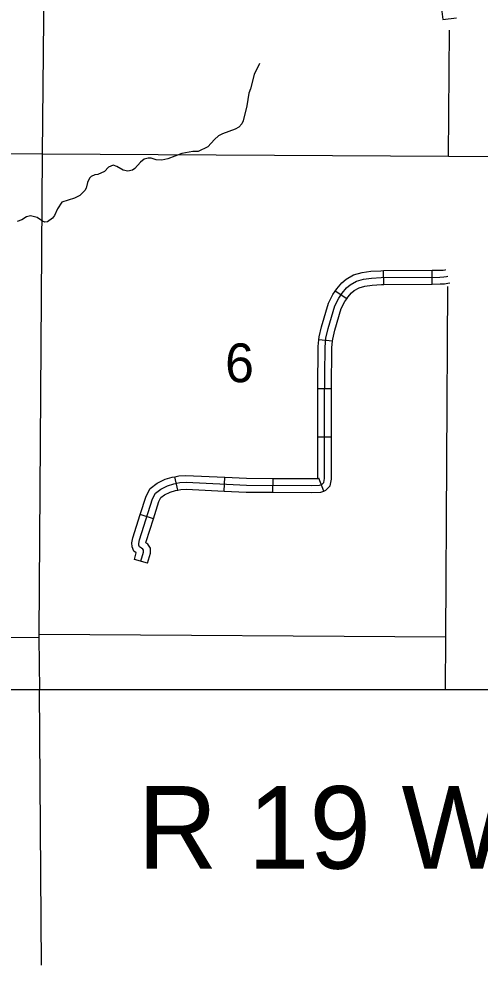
# Model space of a CAD drawing. Extents: x 1374139 to 1377472, y 1168351 to 1170484.
# Drawn here: x 1375695.3 to 1375795.8, y 1168593.8 to 1168800 of the extents above; entities that cross this region are included whole.
import ezdxf

# ---------------------------------------------------------------- set-up
doc = ezdxf.new("R2010")
doc.units = 0
for name, color, linetype in [('14', 7, 'Continuous'), ('26', 7, 'Continuous'), ('Default', 7, 'Continuous')]:
    doc.layers.add(name, color=color, linetype=linetype)

msp = doc.modelspace()

# ---------------------------------------------------------------- linework, layer by layer
at = {"layer": '14'}
msp.add_line((1375700.26, 1168593.79), (1375699.77, 1168653.79), dxfattribs=at)
at = {"layer": '26'}
msp.add_lwpolyline([(1375090, 1169579.43), (1376597.43, 1169579.43), (1376597.43, 1168653.79), (1375090, 1168653.79)], close=True, dxfattribs=at)
at = {"layer": 'Default'}
for p, q in [((1375788.95, 1168770.03), (1375841.85, 1168769.82)), ((1375774.82, 1168742.11), (1375774.8, 1168745.11)), ((1375785.38, 1168742.18), (1375785.36, 1168745.18)), ((1375766.76, 1168738.99), (1375764.27, 1168740.67)), ((1375763.67, 1168729.74), (1375760.69, 1168730.06)), ((1375763.46, 1168719.34), (1375760.46, 1168719.36)), ((1375763.44, 1168708.79), (1375760.44, 1168708.79)), ((1375729.92, 1168697.28), (1375729.3, 1168700.21)), ((1375740.07, 1168697.09), (1375740.21, 1168700.08)), ((1375750.69, 1168696.83), (1375750.7, 1168699.83)), ((1375761.77, 1168697.09), (1375760.68, 1168699.88)), ((1375724.61, 1168691.06), (1375721.75, 1168691.97)), ((1375723.35, 1168681.35), (1375720.47, 1168682.19))]:
    msp.add_line(p, q, dxfattribs=at)
for points in [[(1375700.72, 1168807.29), (1375700.37, 1168770.59)], [(1375787.36, 1168808.46), (1375787.35, 1168808.15), (1375787.5, 1168801.57), (1375787.69, 1168799.87), (1375790.67, 1168800.21)], [(1375788.95, 1168770.03), (1375789.16, 1168797.52)], [(1375747.72, 1168790.26), (1375746.58, 1168787.86), (1375745.78, 1168784.73), (1375745.44, 1168783.8), (1375744.97, 1168781.04), (1375744.22, 1168777.73), (1375743.91, 1168777.08), (1375743.25, 1168776.4), (1375742.44, 1168775.94), (1375739.67, 1168774.91), (1375738.82, 1168774.45), (1375737.94, 1168773.72), (1375736.48, 1168772.06), (1375734.38, 1168771.09), (1375733.22, 1168771.1), (1375730.79, 1168770.64), (1375727.74, 1168769.44), (1375726.49, 1168769.15), (1375725.21, 1168769.24), (1375724.1, 1168769.59), (1375723.5, 1168769.63), (1375722.58, 1168769.43), (1375721.78, 1168768.73), (1375720.61, 1168767.4), (1375720.06, 1168767.02), (1375719.05, 1168766.8), (1375718.06, 1168767.01), (1375716.68, 1168767.84), (1375715.87, 1168768.06), (1375714.85, 1168767.64), (1375713.99, 1168766.71), (1375712.54, 1168766.09), (1375711.89, 1168765.98), (1375711.04, 1168765.59), (1375710.7, 1168765.29), (1375710.23, 1168764.35), (1375709.94, 1168763.08), (1375709.65, 1168762.59), (1375708.6, 1168761.5), (1375707.39, 1168760.87), (1375704.67, 1168760.04), (1375703.71, 1168758.61), (1375703.03, 1168757.11), (1375702.64, 1168756.56), (1375701.54, 1168755.73), (1375700.92, 1168755.65), (1375700.42, 1168755.9), (1375699.3, 1168756.72), (1375697.85, 1168757.04), (1375696.99, 1168756.8), (1375695.97, 1168756.17), (1375694.96, 1168755.79)], [(1375623.44, 1168770.62), (1375700.37, 1168770.59)], [(1375700.37, 1168770.59), (1375699.67, 1168665.86), (1375699.68, 1168665.11), (1375699.77, 1168653.79)], [(1375700.37, 1168770.59), (1375788.95, 1168770.03)], [(1375721.91, 1168681.77), (1375722.49, 1168683.75), (1375722.49, 1168684.18), (1375722.32, 1168684.43), (1375722.02, 1168684.65), (1375721.57, 1168684.95), (1375721.44, 1168685.27), (1375721.42, 1168685.67), (1375721.59, 1168686.48), (1375724.41, 1168695.41), (1375725.05, 1168696.65), (1375726.22, 1168697.52), (1375727.72, 1168698.25), (1375729.08, 1168698.63), (1375730.41, 1168698.91), (1375731.73, 1168699), (1375744.88, 1168698.36), (1375759.06, 1168698.29), (1375760.83, 1168698.33), (1375761.32, 1168698.53), (1375761.75, 1168698.97), (1375761.94, 1168699.81), (1375761.94, 1168716.53), (1375762.03, 1168728.47), (1375762.24, 1168730.43), (1375762.69, 1168732.48), (1375764.16, 1168737.45), (1375765.04, 1168739.13), (1375765.77, 1168740.21), (1375766.73, 1168741.36), (1375767.49, 1168742), (1375768.86, 1168742.79), (1375770.42, 1168743.22), (1375772.14, 1168743.48), (1375774.26, 1168743.6), (1375787.08, 1168743.7), (1375787.92, 1168743.75), (1375788.51, 1168743.82), (1375788.8, 1168743.91)], [(1375764.27, 1168740.67), (1375764.57, 1168741.12), (1375765.66, 1168742.42), (1375766.63, 1168743.23), (1375768.27, 1168744.19), (1375770.11, 1168744.69), (1375771.99, 1168744.97), (1375774.21, 1168745.1), (1375774.8, 1168745.11)], [(1375774.8, 1168745.11), (1375785.36, 1168745.18)], [(1375785.36, 1168745.18), (1375787.03, 1168745.19), (1375787.78, 1168745.24), (1375788.21, 1168745.3), (1375788.38, 1168745.35)], [(1375766.76, 1168738.99), (1375766.98, 1168739.31), (1375767.79, 1168740.3), (1375768.35, 1168740.77), (1375769.44, 1168741.4), (1375770.72, 1168741.75), (1375772.3, 1168741.98), (1375774.31, 1168742.1), (1375774.82, 1168742.11)], [(1375774.82, 1168742.11), (1375785.38, 1168742.18)], [(1375785.38, 1168742.18), (1375787.14, 1168742.2), (1375788.06, 1168742.25), (1375788.82, 1168742.35), (1375789.21, 1168742.46)], [(1375788.32, 1168653.79), (1375788.34, 1168665.24), (1375788.78, 1168741.63)], [(1375760.69, 1168730.06), (1375760.76, 1168730.67), (1375761.24, 1168732.85), (1375762.77, 1168738.02), (1375763.75, 1168739.9), (1375764.27, 1168740.67)], [(1375763.67, 1168729.74), (1375763.72, 1168730.19), (1375764.14, 1168732.11), (1375765.56, 1168736.89), (1375766.33, 1168738.36), (1375766.76, 1168738.99)], [(1375760.46, 1168719.36), (1375760.53, 1168728.55), (1375760.69, 1168730.06)], [(1375763.46, 1168719.34), (1375763.53, 1168728.38), (1375763.67, 1168729.74)], [(1375760.44, 1168708.79), (1375760.44, 1168716.53), (1375760.46, 1168719.36)], [(1375763.44, 1168708.79), (1375763.44, 1168716.52), (1375763.46, 1168719.34)], [(1375760.4, 1168699.77), (1375760.44, 1168699.98), (1375760.44, 1168708.79)], [(1375761.77, 1168697.09), (1375762.18, 1168697.25), (1375763.12, 1168698.24), (1375763.44, 1168699.64), (1375763.44, 1168708.79)], [(1375721.75, 1168691.97), (1375723.02, 1168695.98), (1375723.88, 1168697.64), (1375725.44, 1168698.81), (1375727.18, 1168699.66), (1375728.73, 1168700.09), (1375729.3, 1168700.21)], [(1375729.3, 1168700.21), (1375730.2, 1168700.4), (1375731.72, 1168700.5), (1375740.21, 1168700.08)], [(1375740.21, 1168700.08), (1375744.92, 1168699.86), (1375750.7, 1168699.83)], [(1375750.7, 1168699.83), (1375759.05, 1168699.79), (1375760.53, 1168699.83), (1375760.68, 1168699.88)], [(1375724.61, 1168691.06), (1375725.8, 1168694.83), (1375726.22, 1168695.65), (1375727.01, 1168696.24), (1375728.25, 1168696.84), (1375729.44, 1168697.18), (1375729.92, 1168697.28)], [(1375729.92, 1168697.28), (1375730.61, 1168697.42), (1375731.74, 1168697.49), (1375740.07, 1168697.09)], [(1375740.07, 1168697.09), (1375744.84, 1168696.86), (1375750.69, 1168696.83)], [(1375750.69, 1168696.83), (1375759.08, 1168696.79), (1375761.13, 1168696.84), (1375761.77, 1168697.09)], [(1375720.47, 1168682.19), (1375720.88, 1168683.6), (1375720.35, 1168683.96), (1375719.96, 1168684.94), (1375719.91, 1168685.79), (1375720.14, 1168686.86), (1375721.75, 1168691.97)], [(1375723.35, 1168681.35), (1375723.99, 1168683.54), (1375723.99, 1168684.63), (1375723.41, 1168685.49), (1375722.98, 1168685.8), (1375723.04, 1168686.1), (1375724.61, 1168691.06)], [(1375699.68, 1168665.11), (1375674.82, 1168665.2)], [(1375788.34, 1168665.24), (1375699.67, 1168665.86)]]:
    msp.add_lwpolyline(points, dxfattribs=at)

# ---------------------------------------------------------------- texts
for s, height, p in [('6', 8.45, (1375740.25, 1168720.8)), ('R 19 W', 18, (1375721.18, 1168614.79))]:
    msp.add_text(s, height=height, dxfattribs=at).set_placement(p)

doc.saveas('drawing.dxf')
